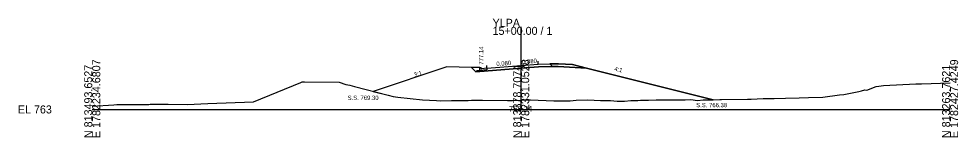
# Model space of a CAD drawing. Extents: x -76 to 1303, y -10 to 9544.
# Drawn here: x -25.7 to 302.8, y 4990.3 to 5031.7 of the extents above; entities that cross this region are included whole.
import ezdxf

# ---------------------------------------------------------------- set-up
doc = ezdxf.new("R2010")
doc.units = 0
for name, color, linetype in [('Exist Cross Section Cell', 7, 'Continuous'), ('Exist XS Center Line Elevation Label', 7, 'Continuous'), ('Exist XS Ground Line', 7, 'Continuous'), ('Prop XS Dump Level', 7, 'Continuous'), ('Prop XS Earthwork Shape', 7, 'Continuous'), ('Prop XS EOT Tick Mark', 7, 'Continuous'), ('Prop XS Finish Grade', 7, 'Continuous'), ('Prop XS Finish Grade CurbGutter', 7, 'Continuous'), ('Prop XS Finish Grade Earthwork', 7, 'Continuous'), ('Prop XS Finish Grade Paved Shoulder', 7, 'Continuous'), ('Prop XS Finish Grade Pavement', 7, 'Continuous'), ('Prop XS Hydro Elevations', 7, 'Continuous'), ('Prop XS Pvmt Edge Slope', 7, 'Continuous'), ('Prop XS SE Text', 7, 'Continuous'), ('Prop XS Side Slope Text', 7, 'Continuous'), ('Prop XS SS Elevation Text', 7, 'Continuous'), ('Prop XS Subgrade CurbGutter', 7, 'Continuous'), ('Prop XS Subgrade Earthwork', 7, 'Continuous'), ('Scratch_Level_3', 7, 'Continuous')]:
    doc.layers.add(name, color=color, linetype=linetype)

msp = doc.modelspace()

# ---------------------------------------------------------------- linework, layer by layer
at = {"layer": 'Exist Cross Section Cell'}
for p, q in [((150, 5000), (150, 5028.86)), ((0, 5000), (150, 5000)), ((150, 5000), (300, 5000))]:
    msp.add_line(p, q, dxfattribs=at)
at = {"layer": 'Exist XS Ground Line'}
for p, q in [((56.44, 5002.67), (72.91, 5009.42)), ((72.91, 5009.42), (73.38, 5009.62)), ((73.38, 5009.62), (74.24, 5009.62)), ((74.24, 5009.62), (86.36, 5009.53)), ((86.36, 5009.53), (88.63, 5008.7)), ((88.63, 5008.7), (90.05, 5008.48)), ((90.05, 5008.48), (91.72, 5008.03)), ((91.72, 5008.03), (103.46, 5004.94)), ((268.97, 5006.51), (270.22, 5006.85)), ((270.22, 5006.85), (270.91, 5006.71)), ((270.91, 5006.71), (274.2, 5008.03)), ((274.2, 5008.03), (275.08, 5008.14)), ((275.08, 5008.14), (276.67, 5008.38)), ((276.67, 5008.38), (288.04, 5008.92)), ((288.04, 5008.92), (289.27, 5008.98)), ((289.27, 5008.98), (289.95, 5009)), ((289.95, 5009), (300, 5009.25)), ((103.46, 5004.94), (105.2, 5004.48)), ((105.2, 5004.48), (106.85, 5004.31)), ((106.85, 5004.31), (115.48, 5003.35)), ((220.08, 5003.49), (229.11, 5003.57)), ((229.11, 5003.57), (230.47, 5003.59)), ((230.47, 5003.59), (234.58, 5003.79)), ((234.58, 5003.79), (237.39, 5003.87)), ((237.39, 5003.87), (238.45, 5003.83)), ((238.45, 5003.83), (242.45, 5003.96)), ((242.45, 5003.96), (247.25, 5004.07)), ((247.25, 5004.07), (250.5, 5004.18)), ((250.5, 5004.18), (255.48, 5004.34)), ((255.48, 5004.34), (261.35, 5005.09)), ((261.35, 5005.09), (262.79, 5005.23)), ((262.79, 5005.23), (268.14, 5006.24)), ((268.14, 5006.24), (268.97, 5006.51)), ((0, 5001.18), (7.59, 5001.65)), ((7.59, 5001.65), (8.61, 5001.73)), ((8.61, 5001.73), (11.9, 5001.7)), ((11.9, 5001.7), (17.55, 5001.7)), ((17.55, 5001.7), (19.75, 5001.73)), ((19.75, 5001.73), (20.31, 5001.8)), ((20.31, 5001.8), (26.53, 5001.87)), ((26.53, 5001.87), (33.24, 5001.74)), ((33.24, 5001.74), (40.47, 5002.05)), ((40.47, 5002.05), (56.44, 5002.67)), ((115.48, 5003.35), (120.44, 5003.07)), ((120.44, 5003.07), (121.74, 5003.05)), ((121.74, 5003.05), (125.66, 5003.09)), ((125.66, 5003.09), (131.44, 5003.15)), ((131.44, 5003.15), (132.63, 5003.24)), ((132.63, 5003.24), (136.44, 5003.21)), ((136.44, 5003.21), (145.23, 5003.16)), ((145.23, 5003.16), (146.92, 5003.07)), ((146.92, 5003.07), (150, 5003.24)), ((150, 5003.24), (152.04, 5003.35)), ((152.04, 5003.35), (152.92, 5003.33)), ((152.92, 5003.33), (153.27, 5003.36)), ((153.27, 5003.36), (161.46, 5003.01)), ((161.46, 5003.01), (166.18, 5003.04)), ((166.18, 5003.04), (167.19, 5003.06)), ((167.19, 5003.06), (169.27, 5003.19)), ((169.27, 5003.19), (173.3, 5003.39)), ((173.3, 5003.39), (177.74, 5003.13)), ((177.74, 5003.13), (181.25, 5003.16)), ((181.25, 5003.16), (183.53, 5002.93)), ((183.53, 5002.93), (186.13, 5002.85)), ((186.13, 5002.85), (188.3, 5003.13)), ((188.3, 5003.13), (190.82, 5003.12)), ((190.82, 5003.12), (191.74, 5003.2)), ((191.74, 5003.2), (194.51, 5003.19)), ((194.51, 5003.19), (197.17, 5003.34)), ((197.17, 5003.34), (198.94, 5003.41)), ((198.94, 5003.41), (205.21, 5003.35)), ((205.21, 5003.35), (206.06, 5003.34)), ((206.06, 5003.34), (207.39, 5003.4)), ((207.39, 5003.4), (209.34, 5003.47)), ((209.34, 5003.47), (211.64, 5003.15)), ((211.64, 5003.15), (213.65, 5003.33)), ((213.65, 5003.33), (216.84, 5003.37)), ((216.84, 5003.37), (219.49, 5003.5)), ((219.49, 5003.5), (220.08, 5003.49))]:
    msp.add_line(p, q, dxfattribs=at)
at = {"layer": 'Prop XS Dump Level'}
for p, q in [((138, 5014.38), (150, 5015.34)), ((150, 5015.34), (156, 5015.82))]:
    msp.add_line(p, q, dxfattribs=at)
at = {"layer": 'Prop XS Earthwork Shape'}
msp.add_lwpolyline([(206.06, 5003.34), (207.39, 5003.4), (209.34, 5003.47), (211.64, 5003.15), (213.65, 5003.33), (216.84, 5003.37), (217.11, 5003.38), (172.83, 5014.45), (162.98, 5015.04), (160.9, 5015), (156.05, 5014.9), (150.07, 5014.43), (134.16, 5013.15), (132.61, 5014.7), (124, 5014.88), (98.27, 5006.3), (103.46, 5004.94), (105.2, 5004.48), (106.85, 5004.31), (115.48, 5003.35), (120.44, 5003.07), (121.74, 5003.05), (125.66, 5003.09), (131.44, 5003.15), (132.63, 5003.24), (136.44, 5003.21), (145.23, 5003.16), (146.92, 5003.07), (150, 5003.24), (152.04, 5003.35), (152.92, 5003.33), (153.27, 5003.36), (161.46, 5003.01), (166.18, 5003.04), (167.19, 5003.06), (169.27, 5003.19), (173.3, 5003.39), (177.74, 5003.13), (181.25, 5003.16), (183.53, 5002.93), (186.13, 5002.85), (188.3, 5003.13), (190.82, 5003.12), (191.74, 5003.2), (194.51, 5003.19), (197.17, 5003.34), (198.94, 5003.41), (205.21, 5003.35)], close=True, dxfattribs=at)
at = {"layer": 'Prop XS EOT Tick Mark'}
for p, q in [((156, 5015.82), (156, 5016.82)), ((138, 5014.38), (138, 5015.38))]:
    msp.add_line(p, q, dxfattribs=at)
at = {"layer": 'Prop XS Finish Grade'}
for p, q in [((135.5, 5014.64), (132.61, 5014.7)), ((160, 5015.9), (163, 5015.96)), ((163, 5015.96), (168, 5015.66)), ((168, 5015.66), (172.83, 5014.45))]:
    msp.add_line(p, q, dxfattribs=at)
at = {"layer": 'Prop XS Finish Grade CurbGutter'}
for p, q in [((135.5, 5014.64), (135.75, 5014.64)), ((135.75, 5014.64), (135.88, 5014.63)), ((135.97, 5014.54), (135.88, 5014.63)), ((136.03, 5014.29), (135.97, 5014.54)), ((136.13, 5014.19), (136.03, 5014.29)), ((136.25, 5014.17), (136.13, 5014.19)), ((138, 5014.38), (136.25, 5014.17))]:
    msp.add_line(p, q, dxfattribs=at)
at = {"layer": 'Prop XS Finish Grade Earthwork'}
for p, q in [((124, 5014.88), (98.27, 5006.3)), ((132.61, 5014.7), (124, 5014.88)), ((172.83, 5014.45), (217.11, 5003.38))]:
    msp.add_line(p, q, dxfattribs=at)
at = {"layer": 'Prop XS Finish Grade Paved Shoulder'}
msp.add_line((156, 5015.82), (160, 5015.9), dxfattribs=at)
at = {"layer": 'Prop XS Finish Grade Pavement'}
for p, q in [((138, 5014.38), (150, 5015.34)), ((150, 5015.34), (156, 5015.82))]:
    msp.add_line(p, q, dxfattribs=at)
at = {"layer": 'Prop XS Pvmt Edge Slope'}
for p, q in [((134.5, 5013.52), (134.16, 5013.15)), ((135.5, 5013.6), (134.5, 5013.52)), ((160, 5015.9), (160.9, 5015))]:
    msp.add_line(p, q, dxfattribs=at)
at = {"layer": 'Prop XS Subgrade CurbGutter'}
for p, q in [((135.5, 5013.6), (135.5, 5014.64)), ((138, 5013.8), (135.5, 5013.6)), ((138, 5014.38), (138, 5013.8))]:
    msp.add_line(p, q, dxfattribs=at)
at = {"layer": 'Prop XS Subgrade Earthwork'}
for p, q in [((134.16, 5013.15), (132.61, 5014.7)), ((134.16, 5013.15), (150.07, 5014.43)), ((150.07, 5014.43), (156.05, 5014.9)), ((156.05, 5014.9), (160.9, 5015)), ((160.9, 5015), (162.98, 5015.04)), ((162.98, 5015.04), (172.83, 5014.45))]:
    msp.add_line(p, q, dxfattribs=at)
at = {"layer": 'Scratch_Level_3'}
for p, q in [((163, 5015.96), (160, 5015.9)), ((160, 5015.9), (160.9, 5015)), ((160.9, 5015), (162.98, 5015.04)), ((162.98, 5015.04), (172.83, 5014.45)), ((168, 5015.66), (163, 5015.96)), ((172.83, 5014.45), (168, 5015.66))]:
    msp.add_line(p, q, dxfattribs=at)

# ---------------------------------------------------------------- texts
at = {"layer": 'Exist Cross Section Cell'}
for s, p in [('YLPA', (140, 5028.86)), ('15+00.00 / 1', (140, 5026.06)), ('EL 763', (-26, 4998.6))]:
    msp.add_text(s, height=2.8, dxfattribs=at).set_placement(p)
for s, p in [('E 1782234.6807', (2.8, 4990)), ('E 1782331.0528', (152.8, 4990)), ('E 1782427.4249', (302.8, 4990)), ('N 813493.6527', (0, 4990)), ('N 813378.7074', (150, 4990)), ('N 813263.7621', (300, 4990))]:
    msp.add_text(s, height=2.8, rotation=90, dxfattribs=at).set_placement(p)
at = {"layer": 'Exist XS Center Line Elevation Label'}
msp.add_text('766.24', height=2, dxfattribs=at).set_placement((145.72, 4999.24))
at = {"layer": 'Prop XS Dump Level'}
msp.add_text('Case4', height=0.04, dxfattribs=at).set_placement((168, 5015.62))
at = {"layer": 'Prop XS Hydro Elevations'}
msp.add_text('777.14', height=1.5, rotation=90, dxfattribs=at).set_placement((136.75, 5015.64))
at = {"layer": 'Prop XS SE Text'}
for p in [(141.38, 5015.15), (150.38, 5015.87)]:
    msp.add_text('0.080', height=1.5, rotation=4.5739, dxfattribs=at).set_placement(p)
at = {"layer": 'Prop XS Side Slope Text'}
for s, rotation, p in [('3:1', 17.8228, (112.73, 5011.29)), ('4:1', 345.9638, (182.45, 5013.59))]:
    msp.add_text(s, height=1.5, rotation=rotation, dxfattribs=at).set_placement(p)
at = {"layer": 'Prop XS SS Elevation Text'}
for s, p in [('S.S. 769.30', (89.31, 5003.32)), ('S.S. 766.38', (211.21, 5000.78))]:
    msp.add_text(s, height=1.5, dxfattribs=at).set_placement(p)

doc.saveas('drawing.dxf')
